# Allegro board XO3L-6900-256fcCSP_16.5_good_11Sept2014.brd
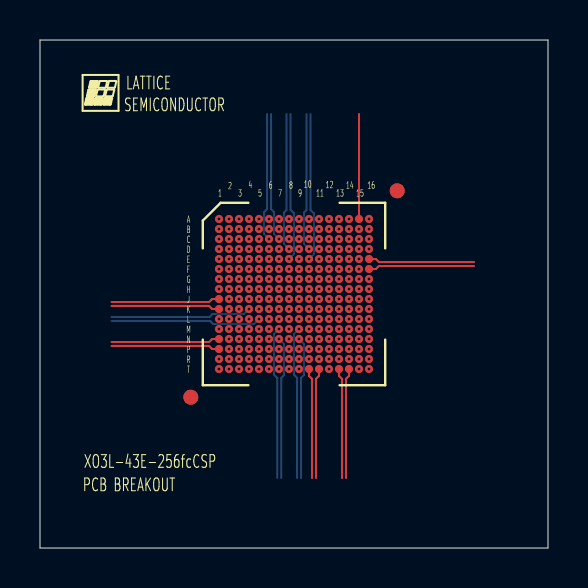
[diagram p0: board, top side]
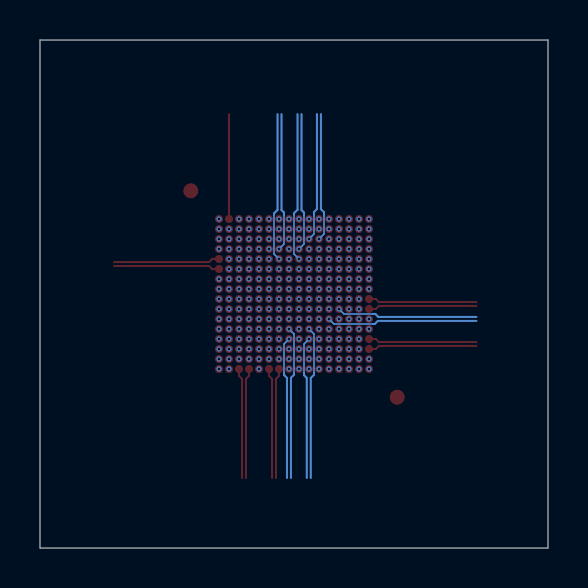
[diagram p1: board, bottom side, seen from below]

Outline 25.4 x 25.4 mm; copper layers: TOP, L2_GND, L3_SIGNAL1, L4_GND, L5_SIGNAL2, L6_PWR, L7_GND, L8_SIGNAL3, L9_GND, L10_SIGNAL4, L11_GND, BOTTOM. Coordinates in mm from the lower left corner of the outline.
Outline path: 0,25.4 25.4,25.4 25.4,0 0,0 0,25.4

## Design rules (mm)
net group CDPB4: nets PB4C PB4D
net group CDPB13: nets PB13C PB13D
net group CDPB18: nets PB18C PB18D
net group CDPB26: nets PB26C PB26D
net group CDPB31: nets PB31C PB31D
net group CDPB38: nets PB38C PB38D
net group CDPL2: nets PL2C PL2D
net group CDPL4: nets PL4C PL4D
net group CDPL6: nets PL6C PL6D
net group CDPL7: nets PL7C PL7D
net group CDPL9: nets PL9C PL9D
net group CDPL10: nets PL10C PL10D
net group CDPL15: nets PL15C PL15D
net group CDPL16: nets PL16C PL16D
net group CDPL19: nets PL19C PL19D
net group CDPL21: nets PL21C PL21D
net group CDPL23: nets PL23C PL23D
net group CDPL25: nets PL25C PL25D
net group CDPR2: nets PR2C PR2D
net group CDPR4: nets PR4C PR4D
net group CDPR6: nets PR6C PR6D
net group CDPR7: nets PR7C PR7D
net group CDPR10: nets PR10C PR10D
net group CDPR11: nets PR11C PR11D
net group CDPR16: nets PR16C PR16D
net group CDPR17: nets PR17C PR17D
net group CDPR19: nets PR19C PR19D
net group CDPR21: nets PR21C PR21D
net group CDPR23: nets PR23C PR23D
net group CDPR24: nets PR24A PR24B
net group CDPR25: nets PR25C PR25D
net group CDPT14: nets PT14C PT14D
net group CDPT17: nets PT17C PT17D
net group CDPT22: nets PT22C PT22D
net group CDPT27: nets PT27C PT27D
net group CDPT36: nets PT36C PT36D
net group PB4: nets PB4A PB4B
net group PB6: nets PB6A PB6B
net group PB7: nets PB7A PB7B
net group PB9: nets PB9A PB9B
net group PB10: nets PB10A PB10B
net group PB12: nets PB12A PB12B
net group PB13: nets PB13A PB13B
net group PB15: nets PB15A PB15B
net group PB16: nets PB16A PB16B
net group PB18: nets PB18A PB18B
net group PB21: nets PB21A PB21B
net group PB23: nets PB23A PB23B
net group PB26: nets PB26A PB26B
net group PB28: nets PB28A PB28B
net group PB29: nets PB29A PB29B
net group PB31: nets PB31A PB31B
net group PB34: nets PB34A PB34B
net group PB35: nets PB35A PB35B
net group PB37: nets PB37A PB37B
net group PB38: nets PB38A PB38B
net group PL3: nets PL3A PL3B
net group PL4: nets PL4A PL4B
net group PL6: nets PL6A PL6B
net group PL8: nets PL8A PL8B
net group PL9: nets PL9A PL9B
net group PL10: nets PL10A PL10B
net group PL11: nets PL11A PL11B
net group PL12: nets PL12A PL12B
net group PL15: nets PL15A PL15B
net group PL17: nets PL17A PL17B
net group PL19: nets PL19A PL19B
net group PL22: nets PL22A PL22B
net group PL24: nets PL24A PL24B
net group PL25: nets PL25A PL25B
net group PR2: nets PR2A PR2B
net group PR3: nets PR3A PR3B
net group PR5: nets PR5A PR5B
net group PR7: nets PR7A PR7B
net group PR9: nets PR9A PR9B
net group PR11: nets PR11A PR11B
net group PR12: nets PR12A PR12B
net group PR15: nets PR15A PR15B
net group PR16: nets PR16A PR16B
net group PR17: nets PR17A PR17B
net group PR18: nets PR18A PR18B
net group PR21: nets PR21A PR21B
net group PR23: nets PR23A PR23B
net group PT9: nets PT9A PT9B
net group PT10: nets PT10A PT10B
net group PT11: nets PT11A PT11B
net group PT12: nets PT12A PT12B
net group PT14: nets PT14A PT14B
net group PT15: nets PT15A PT15B
net group PT16: nets PT16A PT16B
net group PT17: nets PT17A PT17B
net group PT18: nets PT18A PT18B
net group PT21: nets PT21A PT21B
net group PT22: nets PT22A PT22B
net group PT25: nets PT25A PT25B
net group PT26: nets PT26A PT26B
net group PT27: nets PT27A PT27B
net group PT28: nets PT28A PT28B
net group PT32: nets PT32A PT32B
net group PT33: nets PT33A PT33B
net group PT34: nets PT34A PT34B
net group PT35: nets PT35A PT35B
net group PT36: nets PT36A PT36B

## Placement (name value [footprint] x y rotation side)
BGA  -  [BGA256C50P16X16_900X900X100B-1]  12.7 12.7 270 top
NOREF  -  []  1.85 21.54 0 top

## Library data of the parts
BGA = BGA256C50P16X16_900X900X100B-1

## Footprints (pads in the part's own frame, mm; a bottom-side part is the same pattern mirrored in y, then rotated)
BGA256C50P16X16_900X900X100B-1
  round 0.75 smd: (-5.16,5.16) (5.16,-5.16)
  round 0.406 smd: A1(-3.75,-3.75) A2(-3.75,-3.25) A3(-3.75,-2.75) A4(-3.75,-2.25) A5(-3.75,-1.75) A6(-3.75,-1.25) A7(-3.75,-0.75) A8(-3.75,-0.25) A9(-3.75,0.25) A10(-3.75,0.75) A11(-3.75,1.25) A12(-3.75,1.75) A13(-3.75,2.25) A14(-3.75,2.75) A15(-3.75,3.25) A16(-3.75,3.75) B1(-3.25,-3.75) B2(-3.25,-3.25) B3(-3.25,-2.75) B4(-3.25,-2.25) B5(-3.25,-1.75) B6(-3.25,-1.25) B7(-3.25,-0.75) B8(-3.25,-0.25) B9(-3.25,0.25) B10(-3.25,0.75) B11(-3.25,1.25) B12(-3.25,1.75) B13(-3.25,2.25) B14(-3.25,2.75) B15(-3.25,3.25) B16(-3.25,3.75) C1(-2.75,-3.75) C2(-2.75,-3.25) C3(-2.75,-2.75) C4(-2.75,-2.25) C5(-2.75,-1.75) C6(-2.75,-1.25) C7(-2.75,-0.75) C8(-2.75,-0.25) C9(-2.75,0.25) C10(-2.75,0.75) C11(-2.75,1.25) C12(-2.75,1.75) C13(-2.75,2.25) C14(-2.75,2.75) C15(-2.75,3.25) C16(-2.75,3.75) D1(-2.25,-3.75) D2(-2.25,-3.25) D3(-2.25,-2.75) D4(-2.25,-2.25) D5(-2.25,-1.75) D6(-2.25,-1.25) D7(-2.25,-0.75) D8(-2.25,-0.25) D9(-2.25,0.25) D10(-2.25,0.75) D11(-2.25,1.25) D12(-2.25,1.75) D13(-2.25,2.25) D14(-2.25,2.75) D15(-2.25,3.25) D16(-2.25,3.75) E1(-1.75,-3.75) E2(-1.75,-3.25) E3(-1.75,-2.75) E4(-1.75,-2.25) E5(-1.75,-1.75) E6(-1.75,-1.25) E7(-1.75,-0.75) E8(-1.75,-0.25) E9(-1.75,0.25) E10(-1.75,0.75) E11(-1.75,1.25) E12(-1.75,1.75) E13(-1.75,2.25) E14(-1.75,2.75) E15(-1.75,3.25) E16(-1.75,3.75) F1(-1.25,-3.75) F2(-1.25,-3.25) F3(-1.25,-2.75) F4(-1.25,-2.25) F5(-1.25,-1.75) F6(-1.25,-1.25) F7(-1.25,-0.75) F8(-1.25,-0.25) F9(-1.25,0.25) F10(-1.25,0.75) F11(-1.25,1.25) F12(-1.25,1.75) F13(-1.25,2.25) F14(-1.25,2.75) F15(-1.25,3.25) F16(-1.25,3.75) G1(-0.75,-3.75) G2(-0.75,-3.25) G3(-0.75,-2.75) G4(-0.75,-2.25) G5(-0.75,-1.75) G6(-0.75,-1.25) G7(-0.75,-0.75) G8(-0.75,-0.25) G9(-0.75,0.25) G10(-0.75,0.75) G11(-0.75,1.25) G12(-0.75,1.75) G13(-0.75,2.25) G14(-0.75,2.75) G15(-0.75,3.25) G16(-0.75,3.75) H1(-0.25,-3.75) H2(-0.25,-3.25) H3(-0.25,-2.75) H4(-0.25,-2.25) H5(-0.25,-1.75) H6(-0.25,-1.25) H7(-0.25,-0.75) H8(-0.25,-0.25) H9(-0.25,0.25) H10(-0.25,0.75) H11(-0.25,1.25) H12(-0.25,1.75) H13(-0.25,2.25) H14(-0.25,2.75) H15(-0.25,3.25) H16(-0.25,3.75) J1(0.25,-3.75) J2(0.25,-3.25) J3(0.25,-2.75) J4(0.25,-2.25) J5(0.25,-1.75) J6(0.25,-1.25) J7(0.25,-0.75) J8(0.25,-0.25) J9(0.25,0.25) J10(0.25,0.75) J11(0.25,1.25) J12(0.25,1.75) J13(0.25,2.25) J14(0.25,2.75) J15(0.25,3.25) J16(0.25,3.75) K1(0.75,-3.75) K2(0.75,-3.25) K3(0.75,-2.75) K4(0.75,-2.25) K5(0.75,-1.75) K6(0.75,-1.25) K7(0.75,-0.75) K8(0.75,-0.25) K9(0.75,0.25) K10(0.75,0.75) K11(0.75,1.25) K12(0.75,1.75) K13(0.75,2.25) K14(0.75,2.75) K15(0.75,3.25) K16(0.75,3.75) L1(1.25,-3.75) L2(1.25,-3.25) L3(1.25,-2.75) L4(1.25,-2.25) L5(1.25,-1.75) L6(1.25,-1.25) L7(1.25,-0.75) L8(1.25,-0.25) L9(1.25,0.25) L10(1.25,0.75) L11(1.25,1.25) L12(1.25,1.75) L13(1.25,2.25) L14(1.25,2.75) L15(1.25,3.25) L16(1.25,3.75) M1(1.75,-3.75) M2(1.75,-3.25) M3(1.75,-2.75) M4(1.75,-2.25) M5(1.75,-1.75) M6(1.75,-1.25) M7(1.75,-0.75) M8(1.75,-0.25) M9(1.75,0.25) M10(1.75,0.75) M11(1.75,1.25) M12(1.75,1.75) M13(1.75,2.25) M14(1.75,2.75) M15(1.75,3.25) M16(1.75,3.75) N1(2.25,-3.75) N2(2.25,-3.25) N3(2.25,-2.75) N4(2.25,-2.25) N5(2.25,-1.75) N6(2.25,-1.25) N7(2.25,-0.75) N8(2.25,-0.25) N9(2.25,0.25) N10(2.25,0.75) N11(2.25,1.25) N12(2.25,1.75) N13(2.25,2.25) N14(2.25,2.75) N15(2.25,3.25) N16(2.25,3.75) P1(2.75,-3.75) P2(2.75,-3.25) P3(2.75,-2.75) P4(2.75,-2.25) P5(2.75,-1.75) P6(2.75,-1.25) P7(2.75,-0.75) P8(2.75,-0.25) P9(2.75,0.25) P10(2.75,0.75) P11(2.75,1.25) P12(2.75,1.75) P13(2.75,2.25) P14(2.75,2.75) P15(2.75,3.25) P16(2.75,3.75) R1(3.25,-3.75) R2(3.25,-3.25) R3(3.25,-2.75) R4(3.25,-2.25) R5(3.25,-1.75) R6(3.25,-1.25) R7(3.25,-0.75) R8(3.25,-0.25) R9(3.25,0.25) R10(3.25,0.75) R11(3.25,1.25) R12(3.25,1.75) R13(3.25,2.25) R14(3.25,2.75) R15(3.25,3.25) R16(3.25,3.75) T1(3.75,-3.75) T2(3.75,-3.25) T3(3.75,-2.75) T4(3.75,-2.25) T5(3.75,-1.75) T6(3.75,-1.25) T7(3.75,-0.75) T8(3.75,-0.25) T9(3.75,0.25) T10(3.75,0.75) T11(3.75,1.25) T12(3.75,1.75) T13(3.75,2.25) T14(3.75,2.75) T15(3.75,3.25) T16(3.75,3.75)

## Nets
GND: BGA.A1 BGA.A16 BGA.F5 BGA.F10 BGA.G7 BGA.G8 BGA.G9 BGA.G10 BGA.G11 BGA.H6 BGA.H11 BGA.J6 BGA.J11 BGA.K5 BGA.K6 BGA.K7 BGA.K8 BGA.K9 BGA.K10 BGA.K11 BGA.K12 BGA.L6 BGA.T1 BGA.T16
VCC: BGA.H7 BGA.H8 BGA.H9 BGA.H10 BGA.J7 BGA.J8 BGA.J9 BGA.J10
VCCIO0: BGA.F6 BGA.F7 BGA.F8 BGA.F9
VCCIO1: BGA.G6 BGA.H5 BGA.J5
VCCIO2: BGA.L7 BGA.L8 BGA.L9 BGA.L10
VCCIO3: BGA.L11 BGA.L12
VCCIO4: BGA.H12 BGA.J12
VCCIO5: BGA.F11 BGA.G12
PB4A: BGA.P13
PB4B: BGA.R14
PB4C: BGA.N12
PB4D: BGA.M12
PB6A: BGA.T13
PB6B: BGA.T14
PB7A: BGA.P12
PB7B: BGA.R13
PB9A: BGA.M11
PB9B: BGA.N11
PB10A: BGA.R12
PB10B: BGA.P11
PB12A: BGA.T12
PB12B: BGA.R11
PB13A: BGA.N10
PB13B: BGA.M10
PB13C: BGA.P10
PB13D: BGA.R10
PB15A: BGA.T11
PB15B: BGA.T10
PB16A: BGA.T9
PB16B: BGA.R9
PB18A: BGA.N9
PB18B: BGA.M9
PB18C: BGA.P9
PB18D: BGA.P8
PB21A: BGA.R8
PB21B: BGA.T8
PB23A: BGA.T7
PB23B: BGA.R7
PB26A: BGA.N8
PB26B: BGA.M8
PB26C: BGA.T6
PB26D: BGA.R6
PB28A: BGA.P7
PB28B: BGA.P6
PB29A: BGA.T5
PB29B: BGA.R5
PB31A: BGA.N7
PB31B: BGA.M7
PB31C: BGA.T4
PB31D: BGA.R4
PB34A: BGA.R3
PB34B: BGA.T3
PB35A: BGA.M6
PB35B: BGA.N6
PB37A: BGA.R2
PB37B: BGA.T2
PB38A: BGA.M5
PB38B: BGA.N5
PB38C: BGA.P5
PB38D: BGA.P4
PL2C: BGA.D13
PL2D: BGA.C14
PL3A: BGA.B15
PL3B: BGA.B16
PL4A: BGA.C15
PL4B: BGA.C16
PL4C: BGA.D14
PL4D: BGA.E13
PL6A: BGA.D15
PL6B: BGA.D16
PL6C: BGA.F13
PL6D: BGA.F12
PL7C: BGA.E15
PL7D: BGA.E14
PL8A: BGA.G13
PL8B: BGA.G14
PL9A: BGA.F14
PL9B: BGA.F15
PL9C: BGA.E16
PL9D: BGA.F16
PL10A: BGA.G15
PL10B: BGA.G16
PL10C: BGA.H13
PL10D: BGA.H14
PL11A: BGA.H15
PL11B: BGA.H16
PL12A: BGA.J16
PL12B: BGA.J15
PL15A: BGA.K16
PL15B: BGA.K15
PL15C: BGA.J13
PL15D: BGA.J14
PL16C: BGA.L16
PL16D: BGA.K14
PL17A: BGA.M16
PL17B: BGA.L15
PL19A: BGA.N16
PL19B: BGA.M15
PL19C: BGA.K13
PL19D: BGA.L14
PL21C: BGA.M14
PL21D: BGA.L13
PL22A: BGA.P16
PL22B: BGA.N15
PL23C: BGA.P15
PL23D: BGA.R16
PL24A: BGA.R15
PL24B: BGA.T15
PL25A: BGA.M13
PL25B: BGA.N13
PL25C: BGA.N14
PL25D: BGA.P14
PR2A: BGA.A2
PR2B: BGA.B2
PR2C: BGA.D4
PR2D: BGA.E4
PR3A: BGA.B1
PR3B: BGA.C2
PR4C: BGA.D3
PR4D: BGA.C3
PR5A: BGA.D2
PR5B: BGA.C1
PR6C: BGA.F4
PR6D: BGA.G5
PR7A: BGA.D1
PR7B: BGA.E2
PR7C: BGA.F3
PR7D: BGA.E3
PR9A: BGA.G4
PR9B: BGA.G3
PR10C: BGA.E1
PR10D: BGA.F2
PR11A: BGA.G2
PR11B: BGA.F1
PR11C: BGA.H4
PR11D: BGA.H3
PR12A: BGA.H2
PR12B: BGA.G1
PR15A: BGA.H1
PR15B: BGA.J2
PR16A: BGA.J1
PR16B: BGA.K1
PR16C: BGA.J4
PR16D: BGA.J3
PR17A: BGA.K2
PR17B: BGA.L1
PR17C: BGA.L2
PR17D: BGA.K3
PR18A: BGA.M1
PR18B: BGA.M2
PR19C: BGA.K4
PR19D: BGA.L5
PR21A: BGA.N1
PR21B: BGA.P1
PR21C: BGA.L3
PR21D: BGA.L4
PR23A: BGA.M3
PR23B: BGA.N2
PR23C: BGA.R1
PR23D: BGA.P2
PR24A: BGA.N3
PR24B: BGA.M4
PR25C: BGA.P3
PR25D: BGA.N4
PT9A: BGA.A14
PT9B: BGA.B14
PT9C: BGA.A15
PT10A: BGA.E12
PT10B: BGA.E11
PT11A: BGA.A13
PT11B: BGA.B13
PT12A: BGA.C13
PT12B: BGA.D12
PT14A: BGA.E10
PT14B: BGA.D10
PT14C: BGA.D11
PT14D: BGA.C12
PT15A: BGA.B12
PT15B: BGA.A12
PT16A: BGA.A11
PT16B: BGA.B11
PT17A: BGA.B10
PT17B: BGA.A10
PT17C: BGA.C10
PT17D: BGA.C11
PT18A: BGA.B9
PT18B: BGA.A9
PT21A: BGA.E9
PT21B: BGA.D9
PT22A: BGA.C9
PT22B: BGA.C8
PT22C: BGA.A8
PT22D: BGA.B8
PT25A: BGA.D8
PT25B: BGA.E8
PT26A: BGA.B7
PT26B: BGA.A7
PT27A: BGA.D7
PT27B: BGA.E7
PT27C: BGA.C7
PT27D: BGA.C6
PT28A: BGA.A6
PT28B: BGA.B6
PT32A: BGA.A5
PT32B: BGA.B5
PT33A: BGA.D6
PT33B: BGA.C5
PT34A: BGA.E6
PT34B: BGA.E5
PT35A: BGA.A4
PT35B: BGA.B4
PT36A: BGA.A3
PT36B: BGA.B3
PT36C: BGA.C4
PT36D: BGA.D5

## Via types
v1: diameter 0.254, hole 0.152, TOP to BOTTOM, 245 vias

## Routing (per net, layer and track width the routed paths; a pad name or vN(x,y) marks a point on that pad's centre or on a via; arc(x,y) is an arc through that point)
GND:
  vias: v1(8.95,16.45) v1(8.95,8.95) v1(10.95,13.95) v1(10.95,11.95) v1(11.45,12.95) v1(11.45,12.45) v1(11.45,11.95) v1(11.45,11.45) v1(11.95,13.45) v1(11.95,11.95) v1(12.45,13.45) v1(12.45,11.95) v1(12.95,13.45) v1(12.95,11.95) v1(13.45,13.95) v1(13.45,13.45) v1(13.45,11.95) v1(13.95,13.45) v1(13.95,12.95) v1(13.95,12.45) v1(13.95,11.95) v1(14.45,11.95) v1(16.45,16.45) v1(16.45,8.95)
VCC:
  vias: v1(11.95,12.95) v1(11.95,12.45) v1(12.45,12.95) v1(12.45,12.45) v1(12.95,12.95) v1(12.95,12.45) v1(13.45,12.95) v1(13.45,12.45)
VCCIO0:
  vias: v1(11.45,13.95) v1(11.95,13.95) v1(12.45,13.95) v1(12.95,13.95)
VCCIO1:
  vias: v1(10.95,12.95) v1(10.95,12.45) v1(11.45,13.45)
VCCIO2:
  vias: v1(11.95,11.45) v1(12.45,11.45) v1(12.95,11.45) v1(13.45,11.45)
VCCIO3:
  vias: v1(13.95,11.45) v1(14.45,11.45)
VCCIO4:
  vias: v1(14.45,12.95) v1(14.45,12.45)
VCCIO5:
  vias: v1(13.95,13.95) v1(14.45,13.45)
PB4A: length 6.5
  L3_SIGNAL1 w0.081: 15.2,9.27 15.2,9.7 v1(14.95,9.95)
  L3_SIGNAL1 w0.102: 15.2,3.51 15.2,9.27
PB4B: length 6
  L3_SIGNAL1 w0.102: 15.4,3.51 15.4,9.07 15.45,9.12 v1(15.45,9.45)
PB4C: length 7.4
  L10_SIGNAL4 w0.081: v1(14.45,10.45) 14.7,10.2 16.66,10.2
  L10_SIGNAL4 w0.102: 21.69,10.34 16.89,10.34 16.75,10.2 16.66,10.2
PB4D: length 7.4
  L10_SIGNAL4 w0.081: v1(14.45,10.95) 14.7,10.7 16.66,10.7
  L10_SIGNAL4 w0.102: 21.69,10.54 16.92,10.54 16.75,10.7 16.66,10.7
PB6A: length 5.5
  TOP w0.102: BGA.T13 14.95,8.6 15.1,8.45 15.1,3.51
PB6B: length 5.5
  TOP w0.102: BGA.T14 15.45,8.61 15.3,8.45 15.3,3.51
PB7A: length 6.6
  L5_SIGNAL2 w0.081: v1(14.45,9.95) 14.7,9.7 14.7,9.27
  L5_SIGNAL2 w0.102: 14.7,9.27 14.7,9.17 14.75,9.12 14.75,3.51
PB7B: length 5.9
  L5_SIGNAL2 w0.102: v1(14.95,9.45) 14.95,3.51
PB9A: length 7.6
  L8_SIGNAL3 w0.081: 13.7,9.19 13.7,10.7 v1(13.95,10.95)
  L8_SIGNAL3 w0.102: 13.7,9.19 13.7,9.04 13.84,8.9 13.84,3.51
PB9B: length 7.1
  L8_SIGNAL3 w0.081: v1(13.95,10.45) 14.2,10.2 14.2,9.21
  L8_SIGNAL3 w0.102: 14.2,9.21 14.2,9.05 14.04,8.89 14.04,3.51
PB10A: length 6.1
  L10_SIGNAL4 w0.102: v1(14.45,9.45) 14.73,9.17 14.73,8.64 14.55,8.46 14.55,3.51
PB10B: length 6.6
  L10_SIGNAL4 w0.081: v1(13.95,9.95) 14.2,9.7 14.2,8.74
  L10_SIGNAL4 w0.102: 14.36,3.51 14.36,8.47 14.2,8.62 14.2,8.74
PB12A: length 5.9
  L3_SIGNAL1 w0.102: 14.13,3.51 14.13,8.99 14.2,9.06 14.34,9.06 v1(14.45,8.95)
PB12B: length 6
  L3_SIGNAL1 w0.102: 13.93,3.51 13.93,9.07 14.06,9.2 14.06,9.34 v1(13.95,9.45)
PB13A: length 7.1
  L10_SIGNAL4 w0.081: v1(13.45,10.45) 13.2,10.2 13.2,9.2 13.26,9.14
  L10_SIGNAL4 w0.102: 13.26,9.14 13.33,9.07 13.33,3.51
PB13B: length 7.6
  L10_SIGNAL4 w0.081: v1(13.45,10.95) 13.7,10.7 13.7,9.23 13.64,9.17
  L10_SIGNAL4 w0.102: 13.53,3.51 13.53,9.06 13.64,9.17
PB13C: length 6.5
  L5_SIGNAL2 w0.081: v1(13.45,9.95) 13.7,9.7 13.7,9.22
  L5_SIGNAL2 w0.102: 13.7,3.51 13.7,9.22
PB13D: length 6
  L5_SIGNAL2 w0.102: v1(13.45,9.45) 13.45,9.12 13.5,9.07 13.5,3.51
PB15A: length 5.5
  TOP w0.102: 13.8,3.51 13.8,8.45 13.95,8.61 BGA.T11
PB15B: length 5.5
  TOP w0.102: BGA.T10 13.45,8.61 13.6,8.45 13.6,3.51
PB16A: length 5.5
  L3_SIGNAL1 w0.102: 13,3.51 13,8.57 12.95,8.62 v1(12.95,8.95)
PB16B: length 6
  L3_SIGNAL1 w0.081: 13.2,8.72 13.2,9.2 v1(12.95,9.45)
  L3_SIGNAL1 w0.102: 13.2,3.51 13.2,8.72
PB18A: length 7.1
  BOTTOM w0.081: 13.2,8.76 13.2,8.76 13.2,10.2 v1(12.95,10.45)
  BOTTOM w0.102: 13.2,8.76 13.2,8.65 13.05,8.5 13.05,3.51
PB18B: length 7.6
  BOTTOM w0.081: 12.7,8.76 12.7,10.7 v1(12.95,10.95)
  BOTTOM w0.102: 12.7,8.76 12.7,8.66 12.85,8.51 12.85,3.51
PB18C: length 6.6
  L8_SIGNAL3 w0.081: v1(12.95,9.95) 13.2,9.7 13.2,8.71
  L8_SIGNAL3 w0.102: 13.2,8.71 13.2,8.58 13.04,8.42 13.04,3.51
PB18D: length 6.6
  L8_SIGNAL3 w0.081: 12.7,8.71 12.7,9.7 v1(12.45,9.95)
  L8_SIGNAL3 w0.102: 12.84,3.51 12.84,8.41 12.7,8.55 12.7,8.71
PB21A: length 6
  L5_SIGNAL2 w0.081: v1(12.45,9.45) 12.7,9.2 12.7,8.72
  L5_SIGNAL2 w0.102: 12.7,3.51 12.7,8.72
PB21B: length 5.5
  L5_SIGNAL2 w0.102: 12.5,3.51 12.5,8.57 12.45,8.62 v1(12.45,8.95)
PB23A: length 5.5
  L3_SIGNAL1 w0.102: 12,3.51 12,8.57 11.95,8.62 v1(11.95,8.95)
PB23B: length 6
  L3_SIGNAL1 w0.081: v1(11.95,9.45) 12.2,9.2 12.2,8.72
  L3_SIGNAL1 w0.102: 12.2,3.51 12.2,8.72
PB26A: length 7.1
  L10_SIGNAL4 w0.081: 12.64,8.67 12.7,8.73 12.7,10.2 v1(12.45,10.45)
  L10_SIGNAL4 w0.102: 12.64,8.67 12.55,8.58 12.55,3.51
PB26B: length 7.6
  L10_SIGNAL4 w0.081: v1(12.45,10.95) 12.2,10.7 12.2,8.73 12.27,8.66
  L10_SIGNAL4 w0.102: 12.27,8.66 12.35,8.58 12.35,3.51
PB26C: length 5.5
  L5_SIGNAL2 w0.102: v1(11.45,8.95) 11.45,8.62 11.5,8.57 11.5,3.51
PB26D: length 6
  L5_SIGNAL2 w0.081: v1(11.45,9.45) 11.7,9.2 11.7,8.72
  L5_SIGNAL2 w0.102: 11.7,3.51 11.7,8.72
PB28A: length 6.6
  L8_SIGNAL3 w0.081: 12.2,8.71 12.2,9.7 v1(11.95,9.95)
  L8_SIGNAL3 w0.102: 12.04,3.51 12.04,8.42 12.2,8.58 12.2,8.71
PB28B: length 6.6
  L8_SIGNAL3 w0.081: 11.7,8.71 11.7,9.7 v1(11.45,9.95)
  L8_SIGNAL3 w0.102: 11.7,8.71 11.7,8.55 11.84,8.41 11.84,3.51
PB29A: length 5.5
  L3_SIGNAL1 w0.102: v1(10.95,8.95) 10.95,8.62 11,8.57 11,3.51
PB29B: length 6
  L3_SIGNAL1 w0.081: v1(10.95,9.45) 11.2,9.2 11.2,8.72
  L3_SIGNAL1 w0.102: 11.2,3.51 11.2,8.72
PB31A: length 7.1
  BOTTOM w0.081: 12.2,8.76 12.2,8.76 12.2,10.2 v1(11.95,10.45)
  BOTTOM w0.102: 12.2,8.76 12.2,8.64 12.06,8.5 12.06,3.51
PB31B: length 7.6
  BOTTOM w0.081: 11.7,8.76 11.7,10.7 v1(11.95,10.95)
  BOTTOM w0.102: 11.7,8.76 11.7,8.66 11.86,8.5 11.86,3.51
PB31C: length 5.5
  L5_SIGNAL2 w0.102: 10.5,3.51 10.5,8.57 10.45,8.62 v1(10.45,8.95)
PB31D: length 6
  L5_SIGNAL2 w0.081: v1(10.45,9.45) 10.7,9.2 10.7,8.72
  L5_SIGNAL2 w0.102: 10.7,3.51 10.7,8.72
PB34A: length 6
  L3_SIGNAL1 w0.081: 10.2,8.72 10.2,9.2 v1(9.95,9.45)
  L3_SIGNAL1 w0.102: 10.2,3.51 10.2,8.72
PB34B: length 5.5
  L3_SIGNAL1 w0.102: 10,3.51 10,8.57 9.95,8.62 v1(9.95,8.95)
PB35A: length 7.6
  L10_SIGNAL4 w0.081: v1(11.45,10.95) 11.2,10.7 11.2,8.73 11.27,8.66
  L10_SIGNAL4 w0.102: 11.35,3.51 11.35,8.58 11.27,8.66
PB35B: length 7.1
  L10_SIGNAL4 w0.081: 11.64,8.67 11.7,8.73 11.7,10.2 v1(11.45,10.45)
  L10_SIGNAL4 w0.102: 11.55,3.51 11.55,8.58 11.64,8.67
PB37A: length 6
  L5_SIGNAL2 w0.081: v1(9.45,9.45) 9.7,9.2 9.7,8.72
  L5_SIGNAL2 w0.102: 9.7,3.51 9.7,8.72
PB37B: length 5.5
  L5_SIGNAL2 w0.102: 9.5,3.51 9.5,8.57 9.45,8.62 v1(9.45,8.95)
PB38A: length 8
  L10_SIGNAL4 w0.081: v1(10.95,10.95) 10.7,10.7 10.35,10.7 10.2,10.55 10.2,8.75 10.26,8.69
  L10_SIGNAL4 w0.102: 10.26,8.69 10.35,8.6 10.35,3.51
PB38B: length 7.1
  L10_SIGNAL4 w0.081: 10.64,8.69 10.7,8.74 10.7,10.2 v1(10.95,10.45)
  L10_SIGNAL4 w0.102: 10.55,3.51 10.55,8.59 10.64,8.69
PB38C: length 6.6
  L8_SIGNAL3 w0.081: 11.2,8.71 11.2,9.7 v1(10.95,9.95)
  L8_SIGNAL3 w0.102: 11.04,3.51 11.04,8.42 11.2,8.58 11.2,8.71
PB38D: length 6.6
  L8_SIGNAL3 w0.081: 10.7,8.71 10.7,9.7 v1(10.45,9.95)
  L8_SIGNAL3 w0.102: 10.84,3.51 10.84,8.41 10.7,8.55 10.7,8.71
PL2C: length 6.9
  L8_SIGNAL3 w0.081: v1(14.95,14.95) 15.2,15.2 15.2,16.72
  L8_SIGNAL3 w0.102: 15.34,21.69 15.34,17.02 15.2,16.88 15.2,16.72
PL2D: length 6.4
  L8_SIGNAL3 w0.081: v1(15.45,15.45) 15.7,15.7 15.7,16.74
  L8_SIGNAL3 w0.102: 15.54,21.69 15.54,17.02 15.7,16.86 15.7,16.74
PL3A: length 5.8
  L5_SIGNAL2 w0.081: 16.68,16.2 16.2,16.2 v1(15.95,15.95)
  L5_SIGNAL2 w0.102: 21.69,16.2 16.68,16.2
PL3B: length 5.3
  L5_SIGNAL2 w0.102: 21.69,16 16.83,16 16.78,15.95 v1(16.45,15.95)
PL4A: length 5.8
  L3_SIGNAL1 w0.081: 16.68,15.7 16.2,15.7 v1(15.95,15.45)
  L3_SIGNAL1 w0.102: 21.69,15.7 16.68,15.7
PL4B: length 5.3
  L3_SIGNAL1 w0.102: v1(16.45,15.45) 16.78,15.45 16.83,15.5 21.69,15.5
PL4C: length 6.4
  L8_SIGNAL3 w0.081: 16.65,15.2 15.7,15.2 v1(15.45,14.95)
  L8_SIGNAL3 w0.102: 16.65,15.2 16.93,15.2 17.07,15.06 21.69,15.06
PL4D: length 6.9
  L8_SIGNAL3 w0.081: 16.66,14.7 15.2,14.7 v1(14.95,14.45)
  L8_SIGNAL3 w0.102: 21.68,14.86 17.07,14.86 16.91,14.7 16.66,14.7
PL6A: length 5.8
  L5_SIGNAL2 w0.081: 16.68,15.2 16.2,15.2 v1(15.95,14.95)
  L5_SIGNAL2 w0.102: 21.69,15.2 16.68,15.2
PL6B: length 5.3
  L5_SIGNAL2 w0.102: v1(16.45,14.95) 16.78,14.95 16.83,15 21.69,15
PL6C: length 6.9
  L10_SIGNAL4 w0.081: v1(14.95,13.95) 15.2,13.7 16.61,13.7
  L10_SIGNAL4 w0.102: 16.61,13.7 16.76,13.7 16.93,13.53 21.69,13.53
PL6D: length 7.8
  L10_SIGNAL4 w0.081: 16.59,13.2 14.85,13.2 14.7,13.35 14.7,13.7 v1(14.45,13.95)
  L10_SIGNAL4 w0.102: 21.69,13.33 16.92,13.33 16.78,13.2 16.59,13.2
PL7C: length 5.7
  L3_SIGNAL1 w0.102: v1(15.95,14.45) 21.69,14.45
PL7D: length 6.4
  L3_SIGNAL1 w0.081: 16.13,14.7 15.7,14.7 v1(15.45,14.45)
  L3_SIGNAL1 w0.102: 21.69,14.65 16.26,14.65 16.21,14.7 16.13,14.7
PL8A: length 6.9
  L8_SIGNAL3 w0.081: 16.71,13.2 15.2,13.2 v1(14.95,13.45)
  L8_SIGNAL3 w0.102: 21.69,13.34 17,13.34 16.86,13.2 16.71,13.2
PL8B: length 6.4
  L8_SIGNAL3 w0.081: 16.69,13.7 15.7,13.7 v1(15.45,13.45)
  L8_SIGNAL3 w0.102: 16.69,13.7 16.86,13.7 17.02,13.54 21.69,13.54
PL9A: length 6.3
  L5_SIGNAL2 w0.081: 16.18,14.2 15.7,14.2 v1(15.45,13.95)
  L5_SIGNAL2 w0.102: 21.69,14.2 16.18,14.2
PL9B: length 5.8
  L5_SIGNAL2 w0.102: 21.69,14 16.33,14 16.28,13.95 v1(15.95,13.95)
PL9C: length 5.3
  TOP w0.102: 21.69,14.3 16.95,14.3 16.79,14.45 BGA.E16
PL9D: length 5.3
  TOP w0.102: 21.69,14.1 16.95,14.1 16.8,13.95 BGA.F16
PL10A: length 5.8
  L3_SIGNAL1 w0.081: v1(15.95,13.45) 16.2,13.7 16.68,13.7
  L3_SIGNAL1 w0.102: 21.69,13.7 16.68,13.7
PL10B: length 5.3
  L3_SIGNAL1 w0.102: v1(16.45,13.45) 16.78,13.45 16.83,13.5 21.69,13.5
PL10C: length 7.3
  L10_SIGNAL4 w0.081: v1(14.95,12.95) 15.2,12.7 15.2,12.35 15.35,12.2 16.66,12.2
  L10_SIGNAL4 w0.102: 16.66,12.2 16.82,12.2 16.94,12.32 21.69,12.32
PL10D: length 6.4
  L10_SIGNAL4 w0.081: v1(15.45,12.95) 15.7,12.7 16.64,12.7
  L10_SIGNAL4 w0.102: 21.69,12.52 17,12.52 16.82,12.7 16.64,12.7
PL11A: length 5.8
  L5_SIGNAL2 w0.081: 16.68,13.2 16.2,13.2 v1(15.95,12.95)
  L5_SIGNAL2 w0.102: 21.69,13.2 16.68,13.2
PL11B: length 5.3
  L5_SIGNAL2 w0.102: v1(16.45,12.95) 16.78,12.95 16.83,13 21.69,13
PL12A: length 5.3
  L3_SIGNAL1 w0.102: 21.69,12.5 16.83,12.5 16.78,12.45 v1(16.45,12.45)
PL12B: length 5.8
  L3_SIGNAL1 w0.081: v1(15.95,12.45) 16.2,12.7 16.68,12.7
  L3_SIGNAL1 w0.102: 21.69,12.7 16.68,12.7
PL15A: length 5.3
  L5_SIGNAL2 w0.102: v1(16.45,11.95) 16.78,11.95 16.83,12 21.69,12
PL15B: length 5.8
  L5_SIGNAL2 w0.081: v1(15.95,11.95) 16.2,12.2 16.64,12.2
  L5_SIGNAL2 w0.102: 21.69,12.2 16.64,12.2
PL15C: length 6.9
  L8_SIGNAL3 w0.081: 16.71,12.2 15.2,12.2 v1(14.95,12.45)
  L8_SIGNAL3 w0.102: 21.69,12.34 17,12.34 16.86,12.2 16.71,12.2
PL15D: length 6.4
  L8_SIGNAL3 w0.081: 16.69,12.7 15.7,12.7 v1(15.45,12.45)
  L8_SIGNAL3 w0.102: 21.69,12.54 17.02,12.54 16.86,12.7 16.69,12.7
PL16C: length 5.3
  L3_SIGNAL1 w0.102: v1(16.45,11.45) 16.79,11.45 16.84,11.5 21.69,11.5
PL16D: length 6.3
  L3_SIGNAL1 w0.081: v1(15.45,11.95) 15.7,11.7 16.81,11.7
  L3_SIGNAL1 w0.102: 21.69,11.7 16.81,11.7
PL17A: length 5.3
  L5_SIGNAL2 w0.102: 21.69,11 16.83,11 16.78,10.95 v1(16.45,10.95)
PL17B: length 5.8
  L5_SIGNAL2 w0.081: 16.84,11.2 16.2,11.2 v1(15.95,11.45)
  L5_SIGNAL2 w0.102: 21.69,11.2 16.84,11.2
PL19A: length 5.3
  L3_SIGNAL1 w0.102: v1(16.45,10.45) 16.78,10.45 16.83,10.5 21.69,10.5
PL19B: length 5.8
  L3_SIGNAL1 w0.081: v1(15.95,10.95) 16.2,10.7 16.84,10.7
  L3_SIGNAL1 w0.102: 21.69,10.7 16.84,10.7
PL19C: length 6.9
  L10_SIGNAL4 w0.081: v1(14.95,11.95) 15.2,11.7 16.69,11.7
  L10_SIGNAL4 w0.102: 16.69,11.7 16.8,11.7 16.97,11.53 21.69,11.53
PL19D: length 6.4
  L10_SIGNAL4 w0.081: 16.69,11.2 15.7,11.2 v1(15.45,11.45)
  L10_SIGNAL4 w0.102: 21.69,11.33 16.94,11.33 16.81,11.2 16.69,11.2
PL21C: length 6.4
  L8_SIGNAL3 w0.081: v1(15.45,10.95) 15.7,11.2 16.71,11.2
  L8_SIGNAL3 w0.102: 21.69,11.36 17.05,11.36 16.89,11.2 16.71,11.2
PL21D: length 6.9
  L8_SIGNAL3 w0.081: 16.71,11.7 15.2,11.7 v1(14.95,11.45)
  L8_SIGNAL3 w0.102: 16.71,11.7 16.91,11.7 17.05,11.56 21.68,11.56
PL22A: length 5.3
  L5_SIGNAL2 w0.102: v1(16.45,9.95) 16.78,9.95 16.83,10 21.69,10
PL22B: length 5.8
  L5_SIGNAL2 w0.081: 16.84,10.2 16.2,10.2 v1(15.95,10.45)
  L5_SIGNAL2 w0.102: 21.69,10.2 16.84,10.2
PL23C: length 5.8
  L3_SIGNAL1 w0.081: v1(15.95,9.95) 16.2,9.7 16.84,9.7
  L3_SIGNAL1 w0.102: 21.69,9.7 16.84,9.7
PL23D: length 5.3
  L3_SIGNAL1 w0.102: v1(16.45,9.45) 16.78,9.45 16.83,9.5 21.69,9.5
PL24A: length 6
  L5_SIGNAL2 w0.081: v1(15.95,9.45) 16.2,9.2 16.2,8.72
  L5_SIGNAL2 w0.102: 16.2,3.51 16.2,8.72
PL24B: length 5.5
  L5_SIGNAL2 w0.102: v1(15.95,8.95) 15.95,8.62 16,8.57 16,3.51
PL25A: length 7.6
  L8_SIGNAL3 w0.081: 14.7,9.19 14.7,10.7 v1(14.95,10.95)
  L8_SIGNAL3 w0.102: 14.7,9.19 14.7,9.04 14.84,8.9 14.84,3.51
PL25B: length 7.1
  L8_SIGNAL3 w0.081: 15.2,9.21 15.2,10.2 v1(14.95,10.45)
  L8_SIGNAL3 w0.102: 15.2,9.21 15.2,9.05 15.04,8.89 15.04,3.51
PL25C: length 6.4
  L8_SIGNAL3 w0.081: v1(15.45,10.45) 15.7,10.7 16.71,10.7
  L8_SIGNAL3 w0.102: 16.71,10.7 16.89,10.7 17.03,10.56 21.69,10.56
PL25D: length 6.4
  L8_SIGNAL3 w0.081: v1(15.45,9.95) 15.7,10.2 16.71,10.2
  L8_SIGNAL3 w0.102: 16.71,10.2 16.85,10.2 17.02,10.36 21.69,10.36
PR2A: length 5.3
  L3_SIGNAL1 w0.102: v1(9.45,16.45) 9.45,16.78 9.5,16.83 9.5,21.69
PR2B: length 5.8
  L3_SIGNAL1 w0.081: 9.7,16.68 9.7,16.2 v1(9.45,15.95)
  L3_SIGNAL1 w0.102: 9.7,21.69 9.7,16.68
PR2C: length 7
  L10_SIGNAL4 w0.081: 8.71,15.2 10.2,15.2 v1(10.45,14.95)
  L10_SIGNAL4 w0.102: 8.71,15.2 8.6,15.2 8.44,15.04 3.58,15.04
PR2D: length 7
  L10_SIGNAL4 w0.081: v1(10.45,14.45) 10.2,14.7 8.71,14.7
  L10_SIGNAL4 w0.102: 3.58,14.84 8.45,14.84 8.59,14.7 8.71,14.7
PR3A: length 5.4
  L3_SIGNAL1 w0.102: 3.58,15.9 5.45,15.9 8.57,15.9 8.62,15.95 v1(8.95,15.95)
PR3B: length 6
  L3_SIGNAL1 w0.081: v1(9.45,15.45) 9.2,15.7 8.77,15.7
  L3_SIGNAL1 w0.102: 8.77,15.7 5.53,15.7 3.58,15.7
PR4C: length 6.5
  L8_SIGNAL3 w0.081: v1(9.95,14.95) 9.7,15.2 8.71,15.2
  L8_SIGNAL3 w0.102: 8.71,15.2 8.56,15.2 8.4,15.36 3.58,15.36
PR4D: length 6.5
  L8_SIGNAL3 w0.081: 8.71,15.7 9.7,15.7 v1(9.95,15.45)
  L8_SIGNAL3 w0.102: 8.71,15.7 8.55,15.7 8.41,15.55 3.58,15.55
PR5A: length 6
  L5_SIGNAL2 w0.081: v1(9.45,14.95) 9.2,15.2 8.77,15.2
  L5_SIGNAL2 w0.102: 8.77,15.2 5.74,15.2 5.74,15.2 3.58,15.2
PR5B: length 5.4
  L5_SIGNAL2 w0.102: v1(8.95,15.45) 8.62,15.45 8.57,15.4 6.07,15.4 5.66,15.4 3.58,15.4
PR6C: length 7
  L10_SIGNAL4 w0.081: v1(10.45,13.95) 10.2,14.2 8.71,14.2
  L10_SIGNAL4 w0.102: 8.71,14.2 8.6,14.2 8.46,14.06 3.58,14.06
PR6D: length 7.5
  L10_SIGNAL4 w0.081: v1(10.95,13.45) 10.7,13.7 8.71,13.7
  L10_SIGNAL4 w0.102: 8.71,13.7 8.6,13.7 8.45,13.86 3.58,13.86
PR7A: length 5.4
  L3_SIGNAL1 w0.102: 3.58,14.9 5.87,14.9 8.57,14.9 8.62,14.95 v1(8.95,14.95)
PR7B: length 6
  L3_SIGNAL1 w0.081: v1(9.45,14.45) 9.2,14.7 8.77,14.7
  L3_SIGNAL1 w0.102: 8.77,14.7 5.95,14.7 3.58,14.7
PR7C: length 6.5
  L8_SIGNAL3 w0.081: 8.71,14.2 9.7,14.2 v1(9.95,13.95)
  L8_SIGNAL3 w0.102: 3.58,14.36 8.4,14.36 8.56,14.2 8.71,14.2
PR7D: length 6.5
  L8_SIGNAL3 w0.081: 8.71,14.7 9.7,14.7 v1(9.95,14.45)
  L8_SIGNAL3 w0.102: 8.71,14.7 8.55,14.7 8.41,14.55 3.58,14.55
PR9A: length 7
  L8_SIGNAL3 w0.081: 8.69,13.7 10.2,13.7 v1(10.45,13.45)
  L8_SIGNAL3 w0.102: 3.58,13.56 8.4,13.56 8.54,13.7 8.69,13.7
PR9B: length 6.5
  L8_SIGNAL3 w0.081: v1(9.95,13.45) 9.7,13.2 8.71,13.2
  L8_SIGNAL3 w0.102: 3.58,13.36 8.39,13.36 8.55,13.2 8.71,13.2
PR10C: length 5.4
  L5_SIGNAL2 w0.102: 3.58,14.4 6.07,14.4 8.57,14.4 8.62,14.45 v1(8.95,14.45)
PR10D: length 6
  L5_SIGNAL2 w0.081: v1(9.45,13.95) 9.2,14.2 8.77,14.2
  L5_SIGNAL2 w0.102: 3.58,14.2 8.77,14.2
PR11A: length 6
  L3_SIGNAL1 w0.081: v1(9.45,13.45) 9.2,13.7 8.77,13.7
  L3_SIGNAL1 w0.102: 3.58,13.7 8.77,13.7
PR11B: length 5.4
  L3_SIGNAL1 w0.102: v1(8.95,13.95) 8.62,13.95 8.57,13.9 3.58,13.9
PR11C: length 7
  L10_SIGNAL4 w0.081: 8.71,13.2 10.2,13.2 v1(10.45,12.95)
  L10_SIGNAL4 w0.102: 8.71,13.2 8.6,13.2 8.46,13.06 3.58,13.06
PR11D: length 6.5
  L10_SIGNAL4 w0.081: v1(9.95,12.95) 9.7,12.7 8.71,12.7
  L10_SIGNAL4 w0.102: 3.58,12.86 8.45,12.86 8.61,12.7 8.71,12.7
PR12A: length 6
  L5_SIGNAL2 w0.081: v1(9.45,12.95) 9.2,13.2 8.77,13.2
  L5_SIGNAL2 w0.102: 3.58,13.2 8.77,13.2
PR12B: length 5.4
  L5_SIGNAL2 w0.102: v1(8.95,13.45) 8.62,13.45 8.57,13.4 3.58,13.4
PR15A: length 5.8
  L3_SIGNAL1 w0.102: v1(8.95,12.95) 9.06,12.84 9.06,12.7 8.99,12.63 3.58,12.63
PR15B: length 6
  L3_SIGNAL1 w0.102: v1(9.45,12.45) 9.34,12.56 9.2,12.56 9.07,12.43 3.58,12.43
PR16A: length 5.4
  TOP w0.102: 3.58,12.3 8.45,12.3 8.6,12.45 BGA.J1
PR16B: length 5.4
  TOP w0.102: 3.58,12.1 8.45,12.1 8.61,11.95 BGA.K1
PR16C: length 7
  L8_SIGNAL3 w0.081: 9.14,12.24 9.19,12.2 10.2,12.2 v1(10.45,12.45)
  L8_SIGNAL3 w0.102: 9.14,12.24 9.06,12.32 3.58,12.32
PR16D: length 6.5
  L8_SIGNAL3 w0.081: v1(9.95,12.45) 9.7,12.7 9.25,12.7 9.22,12.67
  L8_SIGNAL3 w0.102: 9.22,12.67 9.07,12.52 3.58,12.52
PR17A: length 6
  L5_SIGNAL2 w0.102: 3.58,11.97 9.07,11.97 9.13,11.91 9.2,11.84 9.34,11.84 v1(9.45,11.95)
PR17B: length 5.8
  L5_SIGNAL2 w0.102: 3.58,11.77 8.99,11.77 9.06,11.7 9.06,11.56 v1(8.95,11.45)
PR17C: length 6
  L10_SIGNAL4 w0.102: 3.58,11.82 9.08,11.82 v1(9.45,11.45)
PR17D: length 6.5
  L10_SIGNAL4 w0.081: v1(9.95,11.95) 9.7,12.2 9.23,12.2 9.17,12.14
  L10_SIGNAL4 w0.102: 3.58,12.01 9.04,12.01 9.17,12.14
PR18A: length 5.4
  L3_SIGNAL1 w0.102: v1(8.95,10.95) 8.62,10.95 8.57,11 3.58,11
PR18B: length 6
  L3_SIGNAL1 w0.081: v1(9.45,10.95) 9.2,11.2 8.72,11.2
  L3_SIGNAL1 w0.102: 3.58,11.2 8.72,11.2
PR19C: length 7
  BOTTOM w0.081: 8.76,11.7 8.76,11.7 10.2,11.7 v1(10.45,11.95)
  BOTTOM w0.102: 3.58,11.55 8.48,11.55 8.63,11.7 8.76,11.7
PR19D: length 7.5
  BOTTOM w0.081: v1(10.95,11.45) 10.7,11.2 8.76,11.2
  BOTTOM w0.102: 3.58,11.35 8.51,11.35 8.66,11.2 8.76,11.2
PR21A: length 5.4
  TOP w0.102: 3.58,10.3 8.45,10.3 8.6,10.45 BGA.N1
PR21B: length 5.4
  TOP w0.102: BGA.P1 8.61,9.95 8.45,10.1 3.58,10.1
PR21C: length 6.5
  L8_SIGNAL3 w0.081: 8.71,11.2 9.7,11.2 v1(9.95,11.45)
  L8_SIGNAL3 w0.102: 8.71,11.2 8.55,11.2 8.39,11.36 3.58,11.36
PR21D: length 7
  L8_SIGNAL3 w0.081: v1(10.45,11.45) 10.2,11.7 8.69,11.7
  L8_SIGNAL3 w0.102: 3.58,11.56 8.4,11.56 8.54,11.7 8.69,11.7
PR23A: length 6.5
  L5_SIGNAL2 w0.081: v1(9.95,10.95) 9.7,10.7 9.27,10.7
  L5_SIGNAL2 w0.102: 9.27,10.7 9.17,10.7 9.12,10.65 3.58,10.65
PR23B: length 5.9
  L5_SIGNAL2 w0.102: v1(9.45,10.45) 3.58,10.45
PR23C: length 5.8
  L3_SIGNAL1 w0.102: v1(8.95,9.45) 9.06,9.56 9.06,9.7 8.98,9.78 3.58,9.78
PR23D: length 6
  L3_SIGNAL1 w0.102: 3.58,9.98 9.06,9.98 9.2,9.84 9.34,9.84 v1(9.45,9.95)
PR24A: length 6.5
  L8_SIGNAL3 w0.081: 9.17,10.24 9.21,10.2 9.7,10.2 v1(9.95,10.45)
  L8_SIGNAL3 w0.102: 9.17,10.24 9.06,10.34 3.58,10.34
PR24B: length 7
  L8_SIGNAL3 w0.081: 9.19,10.67 9.23,10.7 10.2,10.7 v1(10.45,10.95)
  L8_SIGNAL3 w0.102: 9.19,10.67 9.07,10.54 3.58,10.54
PR25C: length 6.6
  L8_SIGNAL3 w0.081: v1(9.95,9.95) 9.7,9.7 9.7,8.71
  L8_SIGNAL3 w0.102: 9.7,8.71 9.7,8.55 9.83,8.42 9.83,3.51
PR25D: length 7.1
  L8_SIGNAL3 w0.081: 10.2,8.69 10.2,10.2 v1(10.45,10.45)
  L8_SIGNAL3 w0.102: 10.03,3.51 10.03,8.4 10.2,8.57 10.2,8.69
PT9A: length 5.3
  L3_SIGNAL1 w0.102: 15.5,21.69 15.5,16.83 15.45,16.78 v1(15.45,16.45)
PT9B: length 5.8
  L3_SIGNAL1 w0.081: v1(15.45,15.95) 15.7,16.2 15.7,16.68
  L3_SIGNAL1 w0.102: 15.7,21.69 15.7,16.68
PT9C: length 5.2
  TOP w0.102: BGA.A15 15.95,21.69
PT10A: length 7.4
  L10_SIGNAL4 w0.081: v1(14.45,14.45) 14.7,14.2 16.21,14.2 16.28,14.27
  L10_SIGNAL4 w0.102: 21.69,14.35 16.36,14.35 16.28,14.27
PT10B: length 7.9
  L10_SIGNAL4 w0.081: 16.28,14.61 16.19,14.7 14.2,14.7 v1(13.95,14.45)
  L10_SIGNAL4 w0.102: 21.69,14.55 16.34,14.55 16.28,14.61
PT11A: length 5.3
  L5_SIGNAL2 w0.102: v1(14.95,16.45) 14.95,16.78 15,16.83 15,21.69
PT11B: length 5.8
  L5_SIGNAL2 w0.081: 15.2,16.68 15.2,16.2 v1(14.95,15.95)
  L5_SIGNAL2 w0.102: 15.2,21.69 15.2,16.68
PT12A: length 6.9
  L10_SIGNAL4 w0.081: v1(14.95,15.45) 15.2,15.7 16.69,15.7
  L10_SIGNAL4 w0.102: 21.69,15.54 16.97,15.54 16.81,15.7 16.69,15.7
PT12B: length 7.4
  L10_SIGNAL4 w0.081: 16.69,15.2 14.7,15.2 v1(14.45,14.95)
  L10_SIGNAL4 w0.102: 16.69,15.2 16.8,15.2 16.94,15.34 21.69,15.34
PT14A: length 7.4
  BOTTOM w0.081: v1(13.45,14.45) 13.7,14.7 13.7,16.64
  BOTTOM w0.102: 13.52,21.69 13.52,16.91 13.7,16.73 13.7,16.64
PT14B: length 6.9
  BOTTOM w0.081: 13.2,16.64 13.2,16.64 13.2,15.2 v1(13.45,14.95)
  BOTTOM w0.102: 13.2,16.64 13.2,16.77 13.32,16.9 13.32,21.69
PT14C: length 6.9
  L8_SIGNAL3 w0.081: v1(13.95,14.95) 14.2,15.2 14.2,16.72
  L8_SIGNAL3 w0.102: 14.2,16.72 14.2,16.88 14.34,17.02 14.34,21.69
PT14D: length 6.4
  L8_SIGNAL3 w0.081: 14.7,16.74 14.7,15.7 v1(14.45,15.45)
  L8_SIGNAL3 w0.102: 14.7,16.74 14.7,16.86 14.54,17.02 14.54,21.69
PT15A: length 5.8
  L3_SIGNAL1 w0.081: v1(14.45,15.95) 14.7,16.2 14.7,16.68
  L3_SIGNAL1 w0.102: 14.7,21.69 14.7,16.68
PT15B: length 5.3
  L3_SIGNAL1 w0.102: v1(14.45,16.45) 14.45,16.78 14.5,16.83 14.5,21.69
PT16A: length 5.3
  L5_SIGNAL2 w0.102: 14,21.69 14,16.83 13.95,16.78 v1(13.95,16.45)
PT16B: length 5.8
  L5_SIGNAL2 w0.081: v1(13.95,15.95) 14.2,16.2 14.2,16.68
  L5_SIGNAL2 w0.102: 14.2,21.69 14.2,16.68
PT17A: length 5.8
  L3_SIGNAL1 w0.081: v1(13.45,15.95) 13.7,16.2 13.7,16.69
  L3_SIGNAL1 w0.102: 13.7,21.69 13.7,16.69
PT17B: length 5.3
  L3_SIGNAL1 w0.102: 13.5,21.69 13.5,16.83 13.45,16.78 v1(13.45,16.45)
PT17C: length 6.4
  L8_SIGNAL3 w0.081: 13.2,16.74 13.2,15.7 v1(13.45,15.45)
  L8_SIGNAL3 w0.102: 13.2,16.74 13.2,16.86 13.36,17.02 13.36,21.69
PT17D: length 6.4
  L8_SIGNAL3 w0.081: v1(13.95,15.45) 13.7,15.7 13.7,16.74
  L8_SIGNAL3 w0.102: 13.56,21.69 13.56,17 13.7,16.86 13.7,16.74
PT18A: length 5.8
  L5_SIGNAL2 w0.081: v1(12.95,15.95) 13.2,16.2 13.2,16.68
  L5_SIGNAL2 w0.102: 13.2,21.69 13.2,16.68
PT18B: length 5.3
  L5_SIGNAL2 w0.102: v1(12.95,16.45) 12.95,16.78 13,16.83 13,21.69
PT21A: length 7.4
  L10_SIGNAL4 w0.081: v1(12.95,14.45) 12.7,14.7 12.7,16.69
  L10_SIGNAL4 w0.102: 12.7,16.69 12.7,16.82 12.84,16.96 12.84,21.69
PT21B: length 6.9
  L10_SIGNAL4 w0.081: v1(12.95,14.95) 13.2,15.2 13.2,16.69
  L10_SIGNAL4 w0.102: 13.04,21.69 13.04,16.97 13.2,16.81 13.2,16.69
PT22A: length 6.4
  L8_SIGNAL3 w0.081: v1(12.95,15.45) 12.7,15.7 12.7,16.74
  L8_SIGNAL3 w0.102: 12.7,16.74 12.7,16.86 12.56,17 12.56,21.69
PT22B: length 6.4
  L8_SIGNAL3 w0.081: 12.2,16.74 12.2,15.7 v1(12.45,15.45)
  L8_SIGNAL3 w0.102: 12.2,16.74 12.2,16.86 12.36,17.02 12.36,21.69
PT22C: length 5.3
  L3_SIGNAL1 w0.102: v1(12.45,16.45) 12.45,16.78 12.5,16.83 12.5,21.69
PT22D: length 5.8
  L3_SIGNAL1 w0.081: v1(12.45,15.95) 12.7,16.2 12.7,16.68
  L3_SIGNAL1 w0.102: 12.7,21.69 12.7,16.68
PT25A: length 6.9
  BOTTOM w0.081: 12.2,16.64 12.2,16.64 12.2,15.2 v1(12.45,14.95)
  BOTTOM w0.102: 12.32,21.69 12.32,16.9 12.2,16.77 12.2,16.64
PT25B: length 7.4
  BOTTOM w0.081: 12.7,16.64 12.7,14.7 v1(12.45,14.45)
  BOTTOM w0.102: 12.52,21.69 12.52,16.92 12.7,16.74 12.7,16.64
PT26A: length 5.8
  L5_SIGNAL2 w0.081: v1(11.95,15.95) 12.2,16.2 12.2,16.69
  L5_SIGNAL2 w0.102: 12.2,21.69 12.2,16.69
PT26B: length 5.3
  L5_SIGNAL2 w0.102: 12,21.69 12,16.83 11.95,16.78 v1(11.95,16.45)
PT27A: length 6.9
  L10_SIGNAL4 w0.081: v1(11.95,14.95) 12.2,15.2 12.2,16.69
  L10_SIGNAL4 w0.102: 12.04,21.69 12.04,16.97 12.2,16.81 12.2,16.69
PT27B: length 7.4
  L10_SIGNAL4 w0.081: v1(11.95,14.45) 11.7,14.7 11.7,16.69
  L10_SIGNAL4 w0.102: 11.7,16.69 11.7,16.82 11.84,16.96 11.84,21.69
PT27C: length 6.4
  BOTTOM w0.081: 11.7,16.63 11.7,15.7 v1(11.95,15.45)
  BOTTOM w0.102: 11.55,21.69 11.55,16.95 11.7,16.8 11.7,16.63
PT27D: length 6.4
  BOTTOM w0.081: 11.2,16.6 11.2,15.7 v1(11.45,15.45)
  BOTTOM w0.102: 11.35,21.69 11.35,16.94 11.2,16.79 11.2,16.6
PT28A: length 5.3
  L3_SIGNAL1 w0.102: 11.5,21.69 11.5,16.83 11.45,16.78 v1(11.45,16.45)
PT28B: length 5.8
  L3_SIGNAL1 w0.081: v1(11.45,15.95) 11.7,16.2 11.7,16.68
  L3_SIGNAL1 w0.102: 11.7,21.69 11.7,16.68
PT32A: length 5.3
  L5_SIGNAL2 w0.102: 11,21.69 11,16.83 10.95,16.78 v1(10.95,16.45)
PT32B: length 5.8
  L5_SIGNAL2 w0.081: 11.2,16.68 11.2,16.2 v1(10.95,15.95)
  L5_SIGNAL2 w0.102: 11.2,21.69 11.2,16.68
PT33A: length 6.9
  L8_SIGNAL3 w0.081: 11.7,16.72 11.7,15.2 v1(11.45,14.95)
  L8_SIGNAL3 w0.102: 11.7,16.72 11.7,16.87 11.55,17.02 11.55,21.69
PT33B: length 6.4
  L8_SIGNAL3 w0.081: 11.2,16.74 11.2,15.7 v1(10.95,15.45)
  L8_SIGNAL3 w0.102: 11.35,21.69 11.35,17.02 11.2,16.86 11.2,16.74
PT34A: length 7.4
  L10_SIGNAL4 w0.081: v1(11.45,14.45) 11.2,14.7 11.2,16.69
  L10_SIGNAL4 w0.102: 11.05,21.69 11.05,16.97 11.2,16.82 11.2,16.69
PT34B: length 7.4
  L10_SIGNAL4 w0.081: 10.7,16.69 10.7,14.7 v1(10.95,14.45)
  L10_SIGNAL4 w0.102: 10.85,21.69 10.85,16.97 10.7,16.82 10.7,16.69
PT35A: length 5.3
  L3_SIGNAL1 w0.102: 10.5,21.69 10.5,16.83 10.45,16.78 v1(10.45,16.45)
PT35B: length 5.8
  L3_SIGNAL1 w0.081: v1(10.45,15.95) 10.7,16.2 10.7,16.68
  L3_SIGNAL1 w0.102: 10.7,21.69 10.7,16.68
PT36A: length 5.3
  L5_SIGNAL2 w0.102: v1(9.95,16.45) 9.95,16.78 10,16.83 10,21.69
PT36B: length 5.8
  L5_SIGNAL2 w0.081: 10.2,16.68 10.2,16.2 v1(9.95,15.95)
  L5_SIGNAL2 w0.102: 10.2,21.69 10.2,16.68
PT36C: length 6.4
  L8_SIGNAL3 w0.081: v1(10.45,15.45) 10.2,15.7 10.2,16.74
  L8_SIGNAL3 w0.102: 10.36,21.69 10.36,17.02 10.2,16.86 10.2,16.74
PT36D: length 6.9
  L8_SIGNAL3 w0.081: v1(10.95,14.95) 10.7,15.2 10.7,16.72
  L8_SIGNAL3 w0.102: 10.7,16.72 10.7,16.88 10.56,17.02 10.56,21.69

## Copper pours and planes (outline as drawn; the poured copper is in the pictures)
GND on L2_GND: 3.53,3.45 3.53,21.74 11.15,21.74 11.15,13.65 13.26,13.65 13.26,21.74 21.77,21.74 21.74,3.45
VCC on L6_PWR: 3.53,16.97 3.53,21.74 13.39,21.74 13.39,13.89 14.07,13.21 14.07,11.99 11.53,11.99 11.53,12.95 11.81,13.23 11.81,13.77 9.55,13.77 6.35,16.97
VCCIO0 on L2_GND: 11.25,13.74 11.25,21.74 13.14,21.74 13.14,13.74
VCCIO1 on L6_PWR: 11.71,13.64 11.71,13.28 11.4,12.98 11.4,11.99 8.25,8.84 3.53,8.84 3.53,16.84 6.25,16.84 9.45,13.64
VCCIO2 on L6_PWR: 3.53,3.45 3.53,8.71 8.31,8.71 11.46,11.86 13.64,11.86 13.64,3.45
VCCIO3 on L6_PWR: 13.79,3.45 13.79,11.86 15.65,11.86 19.25,8.25 21.74,8.25 21.74,5.46 21.74,3.45
VCCIO4 on L6_PWR: 14.2,11.99 14.2,13.13 15.21,13.13 17.86,15.77 21.74,15.77 21.74,8.38 19.33,8.38 15.72,11.99
VCCIO5 on L6_PWR: 14.22,13.26 13.51,13.97 13.51,21.74 21.74,21.74 21.74,15.93 17.81,15.93 15.14,13.26

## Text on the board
User.Comments: R.P | REN | 09/02/14 | DWG NO: | XO3L-43E-256FCCSP | REVISION | 1.0 | SHEET | 1 | OF | LATTICE SEMICONDUCTOR CORPORATION | XO3L-43E-256FCCSP PCB BREAKOUT
Ref Des/Silkscreen Top: A | B | C | D | E | F | G | H | J | K | L | M | N | P | R | T | 1 | 2 | 3 | 4 | 5 | 6 | 7 | 8 | 9 | 10 | 11 | 12 | 13 | 14 | 15 | 16 | PCB BREAKOUT | XO3L-43E-256fcCSP | SEMICONDUCTOR | LATTICE
PAGE_OUTLINE: SPECIAL INSTRUCTIONS: | 1/2 OZ CU FOR EXTERNAL AND INTERNAL LAYERS | VIA IN PADS ARE TO BE NON CONDUCTIVE EXPOXY FILLED | GND     PLANE  (L2) | SIGNAL1        (L3) | TOP SIDE       (L1) | GND     PLANE  (L4) | SIGNAL2        (L5) | POWER   PLANE  (L6) | TOP SOLDERMASK | GND     PLANE  (L9) | TOP SILKSCREEN | GND     PLANE  (L7) | SIGNAL4        (L10) | GND     PLANE  (L11) | SIGNAL3        (L8) | BOTTOM SIDE    (L12) | BOTTOM SILKSCREEN | BOTTOM SOLDERMASK | DESIGNED BY: | APPROVED BY: | SIGNATURES         DATE | REV | 1 | INITIAL RELEASE | TRACE WIDTH/SPACE | ESCAPE VIA DRILL | ESCAPE VIA PAD | LAND OPENING | PACKAGE SIZE | LAND PAD | PITCH | DESCRIPTION | 0.102/0.097 | 0.1524 | 0.254 | 9 x 9 | 0.4064 | 0.50 | MM | MM/DD/YYYY | DATE | 354.3x354.3 | 4.00/3.80 | 10.00 | 16.00 | 6.00 | 19.69 | MILS | APPEOVED | X. XXXXX | 12 LAYER STACKUP | PCB BREAKOUT DETAILS | REVISION
User.5: FIGURE | SIZE | 6.0 | DRILL CHART: TOP to BOTTOM | ALL UNITS ARE IN MILS | PLATED | QTY | 245
